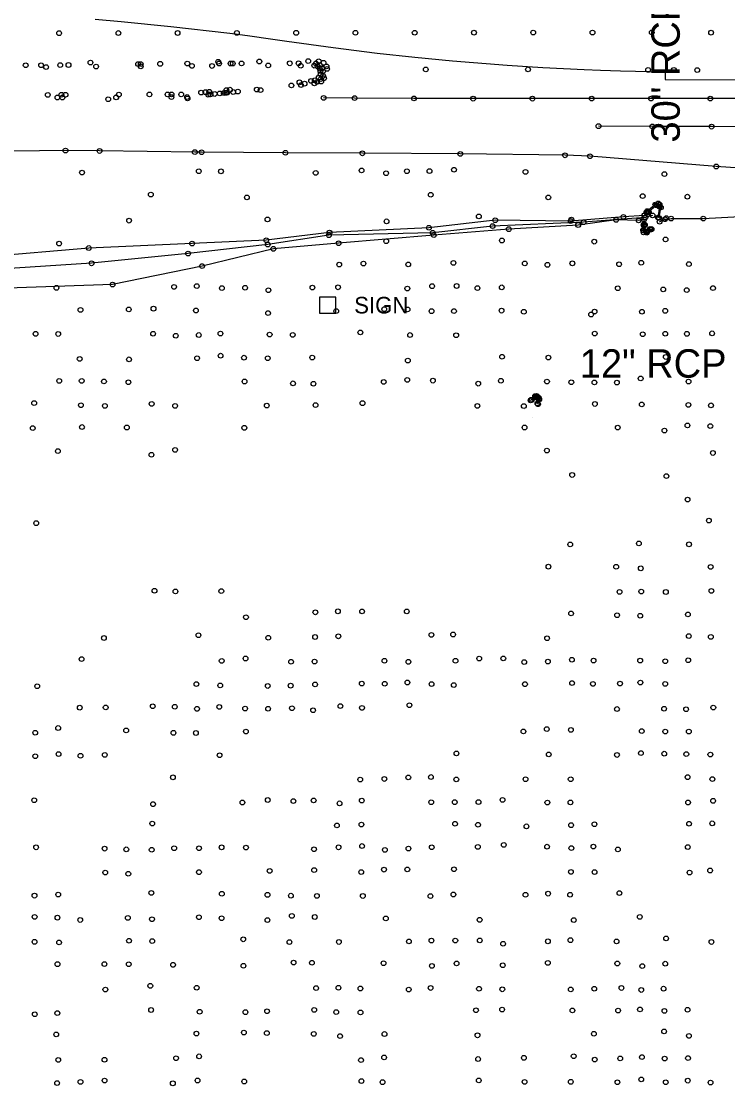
# Model space of a CAD drawing. Extents: x 20503438 to 20508873, y 7964251 to 7984667.
# Drawn here: x 20507449.8 to 20507747.7, y 7970112.2 to 7970561.1 of the extents above; entities that cross this region are included whole.
import ezdxf

# ---------------------------------------------------------------- set-up
doc = ezdxf.new("R2010")
doc.units = 0
for name, color, linetype in [('SurBreakLine', 7, 'Continuous'), ('SurConcreteSlab', 7, 'Continuous'), ('SurDrainageArrowUp', 7, 'Continuous'), ('SurPointsNonDTM', 7, 'Continuous'), ('SurRoadPoints', 7, 'Continuous'), ('SurSurveyPoints', 7, 'Continuous'), ('SurTopOfWater', 7, 'Continuous'), ('SurTxtDrainage', 7, 'Continuous')]:
    doc.layers.add(name, color=color, linetype=linetype)

msp = doc.modelspace()

# ---------------------------------------------------------------- linework, layer by layer
at = {"layer": 'SurBreakLine'}
for points in [[(20507718.76, 7970478.18), (20507719.54, 7970482.63), (20507719, 7970483.84), (20507718.41, 7970484.29), (20507717.2, 7970483.79), (20507713.76, 7970481.08), (20507713.46, 7970480.41), (20507712.59, 7970479.27)], [(20507714.45, 7970480.41), (20507712.59, 7970479.27), (20507703.71, 7970478.63), (20507681.43, 7970476.85), (20507649.67, 7970477.21), (20507621.69, 7970474.02), (20507579.77, 7970471.98), (20507553.1, 7970468.77), (20507521.82, 7970467.38), (20507478.25, 7970465.48), (20507435.23, 7970461.81)], [(20507712.77, 7970475.33), (20507712.45, 7970477.53), (20507710.15, 7970477.14), (20507700.66, 7970477.36), (20507684.65, 7970475.19), (20507655.39, 7970473.44), (20507623.76, 7970470.94), (20507583.62, 7970467.49), (20507556.09, 7970465.15), (20507526.01, 7970457.85), (20507488.26, 7970450.06), (20507444.02, 7970448.57)], [(20507712.77, 7970475.33), (20507712.37, 7970475.42), (20507712.22, 7970475.19), (20507712.05, 7970473.02), (20507712.24, 7970472.1), (20507713.56, 7970471.92), (20507715.22, 7970473.2), (20507715.6, 7970473.5)], [(20507667.71, 7970399.63), (20507668.25, 7970401.67), (20507667.93, 7970402.42), (20507667.48, 7970402.79), (20507667.07, 7970403.11), (20507666.51, 7970403.06), (20507664.78, 7970401.5), (20507664.57, 7970401.25)]]:
    msp.add_lwpolyline(points, dxfattribs=at)
at = {"layer": 'SurConcreteSlab'}
for points in [[(20507480.91, 7970561.94), (20507491.88, 7970561.01), (20507512.87, 7970558.96), (20507537.75, 7970556.05), (20507545.24, 7970555.07), (20507555.94, 7970553.59), (20507561.77, 7970552.74), (20507581.32, 7970550), (20507599.86, 7970547.71), (20507615.78, 7970545.97), (20507631.66, 7970544.45), (20507654.71, 7970542.63), (20507669.72, 7970541.68), (20507687.16, 7970540.82), (20507694.13, 7970540.54), (20507702.56, 7970540.27), (20507721.33, 7970539.72), (20507721.32, 7970536.57), (20507889.99, 7970535.84), (20507890, 7970539.84)], [(20507915.36, 7970528), (20507890.36, 7970528.1), (20507865.36, 7970528.21), (20507840.36, 7970528.31), (20507815.37, 7970528.42), (20507790.37, 7970528.51), (20507765.37, 7970528.5), (20507740.37, 7970528.5), (20507715.37, 7970528.49), (20507690.37, 7970528.49), (20507665.37, 7970528.48), (20507640.37, 7970528.48), (20507615.38, 7970528.59), (20507590.38, 7970528.71), (20507577.31, 7970528.77)], [(20508169.07, 7970514.98), (20508148.11, 7970514.92), (20508123.11, 7970514.84), (20508098.12, 7970514.76), (20508073.12, 7970514.68), (20508040.9, 7970514.94), (20508015.91, 7970515.31), (20507990.91, 7970515.65), (20507965.91, 7970515.75), (20507940.91, 7970515.85), (20507915.92, 7970515.96), (20507890.92, 7970516.06), (20507865.92, 7970516.16), (20507840.92, 7970516.26), (20507815.92, 7970516.37), (20507790.92, 7970516.47), (20507765.92, 7970516.57), (20507740.92, 7970516.67), (20507715.93, 7970516.77), (20507693.23, 7970516.87)], [(20507869.99, 7970500.91), (20507869.89, 7970495.85), (20507869.7, 7970490.88), (20507852.96, 7970492.12), (20507832.94, 7970493.41), (20507812.74, 7970494.79), (20507806, 7970495.66), (20507762.96, 7970498.52), (20507742.87, 7970499.86), (20507689.62, 7970504.2), (20507679.11, 7970504.59), (20507634.93, 7970505.16), (20507593.64, 7970505.43), (20507561.19, 7970505.64), (20507525.85, 7970505.89), (20507522.98, 7970505.92), (20507482.79, 7970506.41), (20507468.43, 7970506.59), (20507413.18, 7970505.94)], [(20507714.2, 7970480.68), (20507717.7, 7970483.54), (20507718.94, 7970482.87), (20507718.31, 7970478.34)], [(20507714.97, 7970473.52), (20507713.5, 7970472.45), (20507712.35, 7970472.91), (20507712.69, 7970475)], [(20507667.45, 7970399.91), (20507667.84, 7970401.92), (20507666.92, 7970402.55), (20507665.05, 7970401.38)]]:
    msp.add_lwpolyline(points, dxfattribs=at)
at = {"layer": 'SurDrainageArrowUp'}
for points in [[(20507719.01, 7970476.57), (20507721.28, 7970477.62), (20507723.84, 7970477.91), (20507737.43, 7970477.9), (20507755.48, 7970478.96), (20507774.94, 7970479.56), (20507794.07, 7970479.65), (20507815.41, 7970479.91), (20507837.68, 7970480.12), (20507857.51, 7970480.48), (20507873.4, 7970480.6), (20507876.74, 7970480.15), (20507883.62, 7970481.46), (20507908.37, 7970484.08)], [(20507716.02, 7970479.24), (20507712.97, 7970478.32), (20507686.95, 7970476.35), (20507648.54, 7970474.75), (20507623.3, 7970471.9), (20507579.51, 7970470.87), (20507553.73, 7970466.92), (20507520.15, 7970463.15), (20507479.41, 7970459.04), (20507440.43, 7970456.6), (20507396.56, 7970452.73), (20507362.35, 7970449.54), (20507347, 7970442.76), (20507335.98, 7970441.55), (20507331.55, 7970441.79), (20507327.55, 7970442.29)]]:
    msp.add_lwpolyline(points, dxfattribs=at)
at = {"layer": 'SurPointsNonDTM'}
for centre in [(20507725, 7970540.58), (20507690.12, 7970437.45)]:
    msp.add_circle(centre, 1, dxfattribs=at)
at = {"layer": 'SurRoadPoints'}
msp.add_lwpolyline([(20507578.97, 7970437.96), (20507578.97, 7970437.96), (20507582.4, 7970437.96), (20507582.4, 7970444.82), (20507575.54, 7970444.82), (20507575.54, 7970437.96), (20507578.97, 7970437.96)], dxfattribs=at)
at = {"layer": 'SurSurveyPoints'}
for centre in [(20507465.72, 7970556.1), (20507490.72, 7970556.15), (20507515.71, 7970556.17), (20507540.71, 7970556.2), (20507565.71, 7970556.23), (20507590.7, 7970556.25), (20507615.7, 7970556.28), (20507640.7, 7970556.31), (20507665.7, 7970556.34), (20507690.69, 7970556.36), (20507715.69, 7970556.39), (20507740.69, 7970556.31), (20507478.95, 7970543.7), (20507499.04, 7970543.06), (20507500.15, 7970543.07), (20507500.15, 7970543.07), (20507508.36, 7970543.16), (20507519.81, 7970543.28), (20507532.84, 7970544.03), (20507533.22, 7970543.3), (20507538.03, 7970543.31), (20507538.99, 7970543.31), (20507542.69, 7970543.32), (20507550.18, 7970544.15), (20507563.02, 7970543.38), (20507566.72, 7970543.38), (20507570.8, 7970544.31), (20507574.06, 7970543.36), (20507575.22, 7970544.26), (20507577.25, 7970543.58), (20507451.64, 7970542.55), (20507458.14, 7970542.55), (20507460.25, 7970541.8), (20507466.21, 7970542.63), (20507469.69, 7970542.67), (20507481.34, 7970542.01), (20507500.15, 7970542.11), (20507500.15, 7970542.11), (20507521.76, 7970542.31), (20507530.24, 7970542.26), (20507553.94, 7970542.47), (20507567.64, 7970542.35), (20507573.36, 7970542.4), (20507574.74, 7970542.16), (20507575.6, 7970541.25), (20507575.75, 7970542.63), (20507575.96, 7970540.11), (20507576.01, 7970538.75), (20507576.69, 7970541.23), (20507577.05, 7970540.03), (20507578.5, 7970542.07), (20507578.75, 7970541.01), (20507578.75, 7970541.01), (20507620.38, 7970540.8), (20507663.5, 7970540.83), (20507714.16, 7970540.62), (20507734.86, 7970540.54), (20507563.7, 7970534.06), (20507567.09, 7970535.36), (20507567.72, 7970534.22), (20507569.27, 7970534.8), (20507572, 7970535.94), (20507573.4, 7970534.94), (20507573.56, 7970536.25), (20507574.53, 7970535.55), (20507575.23, 7970537.35), (20507576.06, 7970536.72), (20507576.26, 7970535.67), (20507577.05, 7970538.07), (20507577.46, 7970537.07), (20507460.94, 7970530.08), (20507466.71, 7970530.11), (20507468.42, 7970530.13), (20507490.95, 7970530.21), (20507503.84, 7970530.24), (20507511.46, 7970530.24), (20507513.17, 7970530.24), (20507517.24, 7970530.24), (20507525.64, 7970531.03), (20507527.48, 7970531.21), (20507528.63, 7970530.15), (20507529.1, 7970531.38), (20507529.58, 7970530.26), (20507531.35, 7970530.45), (20507533.49, 7970530.68), (20507535.18, 7970530.85), (20507535.99, 7970530.94), (20507536.31, 7970532.11), (20507536.58, 7970531), (20507537.78, 7970532.26), (20507539.15, 7970531.27), (20507541.14, 7970531.47), (20507549.09, 7970532.29), (20507550.69, 7970532.07), (20507465.01, 7970528.96), (20507467.09, 7970528.97), (20507486.45, 7970528.25), (20507489.8, 7970529.01), (20507513.11, 7970529.12), (20507519.71, 7970529.17), (20507519.91, 7970528.58), (20507577.31, 7970528.77), (20507590.38, 7970528.71), (20507615.38, 7970528.59), (20507640.37, 7970528.48), (20507665.37, 7970528.48), (20507690.37, 7970528.49), (20507715.37, 7970528.49), (20507740.37, 7970528.5), (20507693.23, 7970516.87), (20507715.93, 7970516.77), (20507740.92, 7970516.67), (20507468.43, 7970506.59), (20507482.79, 7970506.41), (20507522.98, 7970505.92), (20507525.85, 7970505.89), (20507561.19, 7970505.64), (20507593.64, 7970505.43), (20507634.93, 7970505.16), (20507679.11, 7970504.59), (20507689.62, 7970504.2), (20507593.31, 7970498.21), (20507632.28, 7970498.51), (20507742.87, 7970499.86), (20507475.4, 7970497.29), (20507524.65, 7970497.87), (20507534, 7970497.83), (20507573.95, 7970497.17), (20507603.64, 7970497.04), (20507612.41, 7970497.88), (20507621.95, 7970497.94), (20507662.43, 7970497.59), (20507721.03, 7970496.65), (20507504.41, 7970488.04), (20507544.94, 7970486.84), (20507622.47, 7970487.95), (20507672.06, 7970486.84), (20507711.85, 7970487.38), (20507730.71, 7970487.13), (20507713.46, 7970480.41), (20507713.76, 7970481.08), (20507714.2, 7970480.68), (20507714.45, 7970480.41), (20507717.2, 7970483.79), (20507717.7, 7970483.54), (20507718.41, 7970484.29), (20507718.94, 7970482.87), (20507719, 7970483.84), (20507719.54, 7970482.63), (20507495.24, 7970477.03), (20507553.63, 7970477.56), (20507603.82, 7970476.73), (20507642.75, 7970478.83), (20507649.67, 7970477.21), (20507681.43, 7970476.85), (20507681.77, 7970477.47), (20507686.95, 7970476.35), (20507700.66, 7970477.36), (20507703.71, 7970478.63), (20507710.15, 7970477.14), (20507712.45, 7970477.53), (20507712.59, 7970479.27), (20507712.97, 7970478.32), (20507716.02, 7970479.24), (20507718.31, 7970478.34), (20507718.76, 7970478.18), (20507719.01, 7970476.57), (20507721.28, 7970477.62), (20507721.81, 7970478.1), (20507723.84, 7970477.91), (20507737.43, 7970477.9), (20507579.77, 7970471.98), (20507621.69, 7970474.02), (20507623.3, 7970471.9), (20507648.54, 7970474.75), (20507655.39, 7970473.44), (20507684.65, 7970475.19), (20507712.05, 7970473.02), (20507712.22, 7970475.19), (20507712.24, 7970472.1), (20507712.35, 7970472.91), (20507712.37, 7970475.42), (20507712.69, 7970475), (20507712.77, 7970475.33), (20507713.5, 7970472.45), (20507713.56, 7970471.92), (20507714.97, 7970473.52), (20507715.22, 7970473.2), (20507715.6, 7970473.5), (20507465.72, 7970467.35), (20507521.82, 7970467.38), (20507553.1, 7970468.77), (20507553.73, 7970466.92), (20507579.51, 7970470.87), (20507583.62, 7970467.49), (20507603.68, 7970468.34), (20507623.76, 7970470.94), (20507652.49, 7970468.65), (20507691.45, 7970468.17), (20507721.51, 7970469.1), (20507478.25, 7970465.48), (20507520.15, 7970463.15), (20507556.09, 7970465.15), (20507479.41, 7970459.04), (20507526.01, 7970457.85), (20507583.88, 7970458.49), (20507594.09, 7970458.92), (20507613, 7970458.59), (20507632.04, 7970459.22), (20507662.12, 7970458.99), (20507671.7, 7970458.39), (20507682.2, 7970459.03), (20507701.92, 7970458.63), (20507711.23, 7970459.27), (20507731.36, 7970458.69), (20507488.26, 7970450.06), (20507514.22, 7970449.1), (20507523.79, 7970449.41), (20507572.55, 7970448.79), (20507583.38, 7970448.92), (20507623.05, 7970449.4), (20507633.39, 7970449.47), (20507652.41, 7970448.9), (20507464.61, 7970448.69), (20507534.37, 7970448.59), (20507544.17, 7970448.72), (20507554, 7970447.69), (20507612.6, 7970448.39), (20507642.18, 7970448.57), (20507701.36, 7970448.51), (20507720.52, 7970448.04), (20507730.44, 7970447.74), (20507741.52, 7970448.59), (20507505.54, 7970439.91), (20507474.76, 7970439.38), (20507495.12, 7970439.58), (20507523.45, 7970439.13), (20507553.85, 7970438.03), (20507582.61, 7970438.89), (20507602.87, 7970439.7), (20507612.7, 7970439.59), (20507622.81, 7970438.86), (20507632.27, 7970438.87), (20507652.35, 7970439.08), (20507661.74, 7970438.61), (20507691.55, 7970438.67), (20507711.54, 7970438.62), (20507721.36, 7970439), (20507455.82, 7970429.29), (20507465.36, 7970429.23), (20507505.37, 7970429.34), (20507514.94, 7970428.5), (20507524.65, 7970428.79), (20507533.79, 7970429.4), (20507554.53, 7970429), (20507564.26, 7970428.84), (20507592.79, 7970429.91), (20507613.74, 7970428.79), (20507633.19, 7970428.69), (20507691.64, 7970429.4), (20507711.87, 7970429.13), (20507721.39, 7970429.34), (20507730.5, 7970429.3), (20507741.14, 7970429.5), (20507474.41, 7970418.7), (20507495.22, 7970418.53), (20507523.94, 7970419.02), (20507533.85, 7970420.08), (20507543.72, 7970419.24), (20507553.72, 7970419.02), (20507572.47, 7970419.3), (20507612.81, 7970418.03), (20507652.55, 7970419.62), (20507672.09, 7970419.27), (20507721.6, 7970419.54), (20507465.77, 7970409.44), (20507475.26, 7970409.45), (20507484.66, 7970409.22), (20507494.96, 7970408.87), (20507543.94, 7970409.2), (20507564.39, 7970408.41), (20507602.64, 7970409), (20507612.57, 7970409.87), (20507623.39, 7970409.56), (20507652.07, 7970409.49), (20507671.49, 7970409.16), (20507681.76, 7970408.86), (20507691.49, 7970408.78), (20507700.99, 7970408.72), (20507711.01, 7970410.47), (20507731.21, 7970409.18), (20507573, 7970408.25), (20507642.52, 7970408.29), (20507455.21, 7970400.07), (20507504.77, 7970399.75), (20507593.69, 7970400.06), (20507664.57, 7970401.25), (20507664.78, 7970401.5), (20507665.05, 7970401.38), (20507666.51, 7970403.06), (20507666.92, 7970402.55), (20507667.07, 7970403.11), (20507667.45, 7970399.91), (20507667.48, 7970402.79), (20507667.71, 7970399.63), (20507667.84, 7970401.92), (20507667.93, 7970402.42), (20507668.25, 7970401.67), (20507691.71, 7970399.72), (20507711.45, 7970399.53), (20507474.94, 7970399.18), (20507485.05, 7970398.9), (20507514.65, 7970398.92), (20507553.33, 7970399.03), (20507573.9, 7970399.24), (20507642.14, 7970398.88), (20507661.74, 7970398.83), (20507731.14, 7970399.32), (20507740.67, 7970399.13), (20507730.75, 7970390.65), (20507454.6, 7970389.53), (20507475.38, 7970390), (20507494.29, 7970389.8), (20507543.85, 7970389.66), (20507662.03, 7970389.79), (20507701.33, 7970389.74), (20507721.05, 7970388.51), (20507740.38, 7970390.4), (20507465.22, 7970379.84), (20507504.69, 7970378.3), (20507514.67, 7970380.36), (20507671.46, 7970380.08), (20507741.46, 7970379.05), (20507682.12, 7970369.77), (20507721.85, 7970369.29), (20507730.81, 7970359.39), (20507739.79, 7970350.53), (20507456.09, 7970349.45), (20507681.31, 7970340.47), (20507710.27, 7970340.89), (20507731.39, 7970340.52), (20507672.09, 7970331.1), (20507700.68, 7970331.06), (20507711.05, 7970330.4), (20507740.53, 7970330.99), (20507505.96, 7970320.96), (20507514.8, 7970320.64), (20507534.14, 7970320.79), (20507702.09, 7970320.46), (20507711.27, 7970320.62), (20507721.62, 7970320.42), (20507740.82, 7970320.86), (20507544.55, 7970309.77), (20507573.81, 7970311.86), (20507583.3, 7970312.27), (20507593.51, 7970312.25), (20507612.35, 7970312.24), (20507681.65, 7970311.38), (20507701.06, 7970310.62), (20507710.81, 7970310.42), (20507730.95, 7970310.94), (20507484.64, 7970301.02), (20507524.5, 7970302.2), (20507553.95, 7970301.12), (20507573.71, 7970301.44), (20507583.5, 7970301.73), (20507622.75, 7970302.33), (20507631.92, 7970302.49), (20507671.56, 7970300.91), (20507731.29, 7970301.84), (20507740.6, 7970301.49), (20507475.22, 7970292.13), (20507544.38, 7970292.38), (20507642.93, 7970292.35), (20507653.08, 7970292.42), (20507682.01, 7970291.86), (20507534.3, 7970291.37), (20507563.56, 7970290.98), (20507573.47, 7970291.09), (20507602.94, 7970291.4), (20507613.05, 7970290.97), (20507632.91, 7970291.41), (20507661.89, 7970290.87), (20507671.87, 7970291.06), (20507691.15, 7970291.49), (20507710.8, 7970291.49), (20507721.39, 7970291.23), (20507731.07, 7970291.62), (20507456.5, 7970280.68), (20507523.62, 7970281.6), (20507533.68, 7970281.02), (20507553.72, 7970280.79), (20507563.39, 7970280.92), (20507573.69, 7970281.42), (20507593.38, 7970281.78), (20507603.07, 7970281.72), (20507612.62, 7970282.26), (20507622.8, 7970281.6), (20507632.2, 7970281.18), (20507662.22, 7970281.55), (20507682.07, 7970282.02), (20507690.88, 7970281.66), (20507702.29, 7970281.79), (20507710.88, 7970282.24), (20507721.37, 7970281.66), (20507474.42, 7970271.64), (20507485.38, 7970271.73), (20507505.21, 7970272.23), (20507514.53, 7970272), (20507523.9, 7970271.15), (20507533.29, 7970271.94), (20507544.18, 7970271.28), (20507553.88, 7970271.19), (20507563.94, 7970271.41), (20507572.85, 7970270.54), (20507584.35, 7970272.32), (20507593.48, 7970271.56), (20507613.47, 7970272.66), (20507701.02, 7970271.07), (20507720.91, 7970271.19), (20507730.19, 7970270.96), (20507741.65, 7970271.7), (20507455.66, 7970261.07), (20507465.34, 7970263.06), (20507494.01, 7970262.03), (20507513.94, 7970261.03), (20507523.42, 7970260.96), (20507544.53, 7970261.58), (20507661.55, 7970261.61), (20507671.4, 7970262.59), (20507681.57, 7970262.24), (20507711.46, 7970261.75), (20507721.39, 7970261.57), (20507731.33, 7970261.56), (20507465.5, 7970252.07), (20507474.75, 7970251.35), (20507484.98, 7970251.73), (20507533.43, 7970251.56), (20507633.3, 7970252.36), (20507672.23, 7970251.93), (20507701.02, 7970251.69), (20507711.13, 7970252.47), (20507720.96, 7970252.23), (20507730.26, 7970252.04), (20507740.4, 7970251.86), (20507455.68, 7970251.17), (20507622.56, 7970242.39), (20507730.8, 7970242.33), (20507513.74, 7970242.26), (20507592.74, 7970241.32), (20507602.91, 7970241.57), (20507613.01, 7970242.24), (20507633.26, 7970241.39), (20507662.46, 7970241.46), (20507681.5, 7970241.45), (20507741.24, 7970241.51), (20507455.24, 7970232.62), (20507505.35, 7970230.95), (20507543.04, 7970231.64), (20507553.71, 7970232.7), (20507564.54, 7970232.25), (20507573.08, 7970232.53), (20507584.02, 7970231.28), (20507593.38, 7970232.44), (20507622.68, 7970231.76), (20507632.59, 7970231.78), (20507642.61, 7970231.84), (20507652.77, 7970232.74), (20507671.66, 7970231.63), (20507681.39, 7970231.69), (20507731, 7970231.65), (20507741.55, 7970232.35), (20507505.03, 7970222.76), (20507582.91, 7970221.98), (20507593.22, 7970222.36), (20507632.72, 7970222.68), (20507642.41, 7970222.26), (20507662.85, 7970221.58), (20507681.68, 7970222.08), (20507691.5, 7970222.48), (20507731.41, 7970222.69), (20507741.19, 7970222.85), (20507456.03, 7970212.75), (20507484.92, 7970212.19), (20507494.08, 7970211.88), (20507504.78, 7970211.7), (20507514.26, 7970212.36), (20507524.74, 7970212.34), (20507534.26, 7970212.74), (20507544.54, 7970212.63), (20507573.25, 7970211.92), (20507583.6, 7970212.75), (20507593.5, 7970213.29), (20507603.13, 7970211.65), (20507613.07, 7970212.21), (20507622.89, 7970212.77), (20507642.34, 7970212.93), (20507653.28, 7970213.76), (20507671.53, 7970213.01), (20507681.78, 7970212.42), (20507691.07, 7970213.05), (20507701.4, 7970211.85), (20507730.87, 7970212.86), (20507485.2, 7970202.1), (20507524.72, 7970202.26), (20507554.54, 7970202.78), (20507573.31, 7970203.12), (20507593.16, 7970202.31), (20507602.76, 7970203.33), (20507612.59, 7970203.44), (20507632.27, 7970203.48), (20507681.6, 7970202.36), (20507691.56, 7970202.31), (20507731.64, 7970202.1), (20507740.29, 7970202.97), (20507494.92, 7970201.58), (20507504.63, 7970193.5), (20507534.36, 7970193.16), (20507671.96, 7970193.21), (20507702.04, 7970193.46), (20507455.35, 7970192.37), (20507465.35, 7970192.82), (20507553.62, 7970192.71), (20507563.49, 7970192.34), (20507574.44, 7970192.24), (20507593.83, 7970192.23), (20507622.34, 7970192.18), (20507632.02, 7970192.85), (20507662.43, 7970192.74), (20507681.24, 7970192.75), (20507455.41, 7970183.41), (20507465.02, 7970183.08), (20507474.65, 7970182.1), (20507494.71, 7970182.99), (20507504.91, 7970182.42), (20507524.7, 7970183.27), (20507534.26, 7970182.84), (20507553.61, 7970182.07), (20507563.89, 7970183.84), (20507573.55, 7970183.36), (20507603.53, 7970182.76), (20507643.1, 7970182.17), (20507682.79, 7970182.07), (20507710.64, 7970183.41), (20507455.39, 7970172.89), (20507465.71, 7970172.63), (20507495.22, 7970173.35), (20507504.99, 7970173.2), (20507543.41, 7970173.95), (20507562.88, 7970172.79), (20507583.72, 7970172.82), (20507613.28, 7970173.07), (20507622.78, 7970173.4), (20507632.83, 7970173.41), (20507643.15, 7970173.49), (20507653, 7970172.07), (20507671.89, 7970173.1), (20507681.39, 7970173.59), (20507700.85, 7970173.07), (20507721.74, 7970174.34), (20507740.85, 7970172.82), (20507465.06, 7970163.47), (20507484.84, 7970163.51), (20507495.09, 7970163.43), (20507513.79, 7970163.19), (20507543.48, 7970162.78), (20507564.63, 7970164.13), (20507572.37, 7970164.05), (20507602.56, 7970163.86), (20507622.95, 7970162.72), (20507633.38, 7970163.78), (20507652.85, 7970163), (20507671.85, 7970164.01), (20507701.16, 7970163.75), (20507711.69, 7970162.64), (20507721.38, 7970163.67), (20507485.24, 7970152.77), (20507504.2, 7970154.33), (20507523.76, 7970153.53), (20507574.14, 7970153.37), (20507583.53, 7970153.5), (20507592.8, 7970153.2), (20507613.18, 7970152.76), (20507622.43, 7970153.43), (20507642.83, 7970153.1), (20507652.65, 7970152.86), (20507681.51, 7970152.8), (20507691.45, 7970153.11), (20507702.9, 7970153.42), (20507711.26, 7970152.58), (20507720.67, 7970153.12), (20507504.55, 7970144.14), (20507553.43, 7970143.6), (20507573.33, 7970144.19), (20507641.55, 7970144.02), (20507652.58, 7970144.32), (20507682.22, 7970143.94), (20507701.49, 7970143.89), (20507710.73, 7970144.38), (20507721.03, 7970143.74), (20507730.77, 7970144.22), (20507455.48, 7970142.33), (20507464.98, 7970142.81), (20507525.01, 7970143.38), (20507544.32, 7970143.22), (20507582.61, 7970143.24), (20507592.85, 7970143.1), (20507543.67, 7970134.62), (20507720.89, 7970135.12), (20507464.52, 7970133.85), (20507523.64, 7970134.18), (20507553.34, 7970134.4), (20507573.14, 7970134.06), (20507584.23, 7970133.12), (20507602.97, 7970134), (20507642.19, 7970133.46), (20507691.28, 7970134.11), (20507731.37, 7970133.22), (20507465.38, 7970123.08), (20507484.88, 7970123.17), (20507515.05, 7970123.8), (20507524.79, 7970124.59), (20507593.07, 7970123.01), (20507602.8, 7970124.14), (20507642.44, 7970123.46), (20507661.77, 7970123.97), (20507682.76, 7970124.63), (20507691.63, 7970123.21), (20507702.39, 7970123.71), (20507711.55, 7970124.28), (20507721.13, 7970123.63), (20507730.98, 7970123.84), (20507464.88, 7970113.32), (20507474.75, 7970113.82), (20507484.93, 7970114.38), (20507513.7, 7970113.21), (20507524.12, 7970114.41), (20507543.8, 7970113.99), (20507593.24, 7970114.17), (20507602.15, 7970113.71), (20507642.72, 7970114.43), (20507662.06, 7970113.82), (20507681.54, 7970113.84), (20507701.19, 7970113.66), (20507711.26, 7970114.88), (20507721.57, 7970113.65), (20507730.89, 7970114.34), (20507740.49, 7970113.54)]:
    msp.add_circle(centre, 1, dxfattribs=at)
at = {"layer": 'SurTopOfWater'}
for points in [[(20507661.85, 7970397.25), (20507661.89, 7970397.25), (20507661.89, 7970397.29), (20507661.85, 7970397.29)], [(20507661.87, 7970397.3), (20507661.87, 7970397.3), (20507661.87, 7970397.26), (20507661.87, 7970397.26)], [(20507661.87, 7970397.3), (20507661.87, 7970397.3), (20507661.87, 7970397.28), (20507661.87, 7970397.28)], [(20507661.87, 7970397.28), (20507661.87, 7970397.28), (20507661.87, 7970397.27), (20507661.87, 7970397.27)], [(20507661.87, 7970397.27), (20507661.87, 7970397.27), (20507661.87, 7970397.26), (20507661.87, 7970397.26)], [(20507665.36, 7970393.97), (20507665.4, 7970393.97), (20507665.4, 7970394.01), (20507665.36, 7970394.01)], [(20507665.38, 7970394.02), (20507665.38, 7970394.02), (20507665.38, 7970393.98), (20507665.38, 7970393.98)], [(20507665.38, 7970394.02), (20507665.38, 7970394.02), (20507665.38, 7970394), (20507665.38, 7970394)], [(20507665.38, 7970394), (20507665.38, 7970394), (20507665.38, 7970393.99), (20507665.38, 7970393.99)], [(20507665.38, 7970393.99), (20507665.38, 7970393.99), (20507665.38, 7970393.98), (20507665.38, 7970393.98)]]:
    msp.add_lwpolyline(points, close=True, dxfattribs=at)
for centre in [(20507661.86, 7970397.27), (20507661.87, 7970397.27), (20507661.88, 7970397.27), (20507665.37, 7970393.99), (20507665.38, 7970393.99), (20507665.39, 7970393.99)]:
    msp.add_arc(centre, 0.00586, 186.3566, 5.6839, dxfattribs=at)

# ---------------------------------------------------------------- texts
at = {"layer": 'SurRoadPoints'}
msp.add_text('SIGN', height=6.995, rotation=360, dxfattribs=at).set_placement((20507590.18, 7970437.89))
at = {"layer": 'SurTxtDrainage'}
msp.add_text('30" RCP', height=12, rotation=90, dxfattribs=at).set_placement((20507727.51, 7970509.96))
msp.add_text('12" RCP', height=12, dxfattribs=at).set_placement((20507685.34, 7970410.79))

doc.saveas('drawing.dxf')
